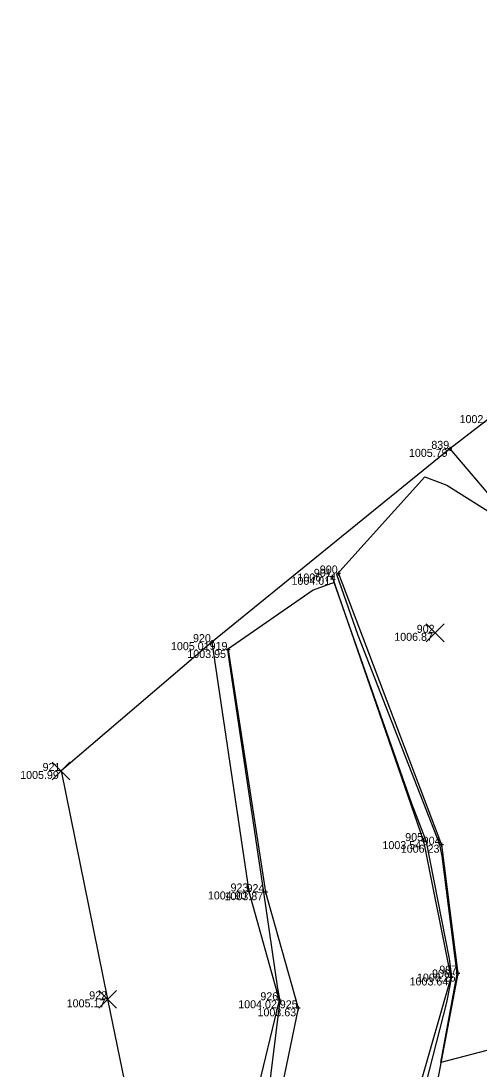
# Model space of a CAD drawing. Extents: x 2354693 to 2355622, y 637071 to 710080.
# Drawn here: x 2355052.4 to 2355121.1, y 709416.4 to 709573.6 of the extents above; entities that cross this region are included whole.
import ezdxf

# ---------------------------------------------------------------- set-up
doc = ezdxf.new("R2010")
doc.units = 0
for name, color, linetype in [('Default', 7, 'Continuous'), ('DT_X_Contour_Minor', 7, 'Continuous'), ('HY_X_Water_Edge', 7, 'Continuous'), ('SV_X_Random_Point', 7, 'Continuous'), ('SV_X_Shot_Marker', 7, 'Continuous'), ('SV_X_Text_Elevation', 7, 'Continuous'), ('SV_X_Text_Name', 7, 'Continuous'), ('SV_X_Toe_of_Slope', 7, 'Continuous'), ('SV_X_Top_of_Bank', 7, 'Continuous')]:
    doc.layers.add(name, color=color, linetype=linetype)

msp = doc.modelspace()

# ---------------------------------------------------------------- linework, layer by layer
at = {"layer": 'Default'}
msp.add_lwpolyline([(2355192.85, 709575.71), (2355160.05, 709542.81), (2355116.76, 709509.42), (2355081.06, 709480.43), (2355058.46, 709461.11), (2355065.45, 709426.86), (2355078.86, 709361.48), (2355116.19, 709325.77), (2355146.4, 709319.01), (2355178.16, 709243.86), (2355227.43, 709181.3), (2355213.36, 709127.54), (2355205.69, 709069.16), (2355203.89, 709062.28), (2355168.12, 708973.83)], dxfattribs=at)
msp.add_lwpolyline([(2355192.85, 709575.71), (2355160.05, 709542.81), (2355116.76, 709509.42), (2355081.06, 709480.43), (2355058.46, 709461.11), (2355065.45, 709426.86), (2355078.86, 709361.48), (2355116.19, 709325.77), (2355146.4, 709319.01), (2355178.16, 709243.86), (2355227.43, 709181.3), (2355213.36, 709127.54), (2355205.69, 709069.16), (2355203.89, 709062.28), (2355168.12, 708973.83)], dxfattribs=at)
at = {"layer": 'DT_X_Contour_Minor'}
for points in [[(2355136.74, 709486.86), (2355138.47, 709485.41), (2355148.81, 709475.1), (2355149.61, 709471.69), (2355151.16, 709446.51), (2355144.05, 709443.89), (2355145.69, 709438.94), (2355130.58, 709421.31), (2355115.44, 709417.4), (2355117.87, 709430.67), (2355115.64, 709448.31), (2355115.29, 709450.09), (2355103.02, 709481.45), (2355099.82, 709490.6), (2355113.01, 709505.22), (2355116.33, 709503.95), (2355127.34, 709497.01), (2355136.74, 709486.86)], [(2355136.74, 709486.86), (2355138.47, 709485.41), (2355148.81, 709475.1), (2355149.61, 709471.69), (2355151.16, 709446.51), (2355144.05, 709443.89), (2355145.69, 709438.94), (2355130.58, 709421.31), (2355115.44, 709417.4), (2355117.87, 709430.67), (2355115.64, 709448.31), (2355115.29, 709450.09), (2355103.02, 709481.45), (2355099.82, 709490.6), (2355113.01, 709505.22), (2355116.33, 709503.95), (2355127.34, 709497.01), (2355136.74, 709486.86)], [(2355111.69, 709408.23), (2355116.34, 709426.38), (2355117.05, 709430.22), (2355116.71, 709432.93), (2355113.29, 709450.49), (2355111.01, 709456.32), (2355099.44, 709489.36), (2355096.29, 709488.23), (2355083.41, 709479.32), (2355083.67, 709477.5), (2355088.8, 709442.95), (2355090.93, 709428.49), (2355091.27, 709426.68), (2355089.28, 709410.54)], [(2355111.69, 709408.23), (2355116.34, 709426.38), (2355117.05, 709430.22), (2355116.71, 709432.93), (2355113.29, 709450.49), (2355111.01, 709456.32), (2355099.44, 709489.36), (2355096.29, 709488.23), (2355083.41, 709479.32), (2355083.67, 709477.5), (2355088.8, 709442.95), (2355090.93, 709428.49), (2355091.27, 709426.68), (2355089.28, 709410.54)]]:
    msp.add_lwpolyline(points, dxfattribs=at)
at = {"layer": 'HY_X_Water_Edge'}
msp.add_lwpolyline([(2355099.14, 709490.23), (2355112.83, 709450.59), (2355116.9, 709430.14), (2355110.74, 709408.55), (2355107.27, 709364.38), (2355126.09, 709328.02), (2355146.4, 709319.01), (2355178.16, 709243.86), (2355207.27, 709238.41), (2355228.23, 709233.04), (2355237.12, 709206.89), (2355247.9, 709203.67), (2355256.61, 709243.12), (2355267.3, 709285.53), (2355279.14, 709298.91), (2355298.35, 709321.78), (2355310.42, 709328.49), (2355317.24, 709340.56)], dxfattribs=at)
at = {"layer": 'SV_X_Random_Point'}
for p, q in [((2355113.23, 709480.49), (2355115.9, 709483.16)), ((2355113.23, 709483.16), (2355115.9, 709480.49)), ((2355057.12, 709459.78), (2355059.79, 709462.45)), ((2355057.12, 709462.45), (2355059.79, 709459.78)), ((2355064.11, 709425.52), (2355066.78, 709428.19)), ((2355064.11, 709428.19), (2355066.78, 709425.52))]:
    msp.add_line(p, q, dxfattribs=at)
at = {"layer": 'SV_X_Shot_Marker'}
for p, q in [((2355117.06, 709509.42), (2355116.46, 709509.42)), ((2355116.76, 709509.72), (2355116.76, 709509.12)), ((2355099.14, 709490.53), (2355099.14, 709489.93)), ((2355100.38, 709490.73), (2355099.78, 709490.73)), ((2355100.08, 709491.03), (2355100.08, 709490.43)), ((2355099.44, 709490.23), (2355098.84, 709490.23)), ((2355081.36, 709480.43), (2355080.76, 709480.43)), ((2355081.06, 709480.73), (2355081.06, 709480.13)), ((2355083.82, 709479.26), (2355083.22, 709479.26)), ((2355083.52, 709479.56), (2355083.52, 709478.96)), ((2355113.13, 709450.59), (2355112.53, 709450.59)), ((2355112.83, 709450.89), (2355112.83, 709450.29)), ((2355115.82, 709450.05), (2355115.22, 709450.05)), ((2355115.52, 709450.35), (2355115.52, 709449.75)), ((2355086.64, 709443.34), (2355086.64, 709442.74)), ((2355089.1, 709443.23), (2355089.1, 709442.63)), ((2355086.94, 709443.04), (2355086.34, 709443.04)), ((2355089.4, 709442.93), (2355088.8, 709442.93)), ((2355118.28, 709430.72), (2355117.68, 709430.72)), ((2355117.98, 709431.02), (2355117.98, 709430.42)), ((2355117.2, 709430.14), (2355116.6, 709430.14)), ((2355116.9, 709430.44), (2355116.9, 709429.84)), ((2355091.45, 709426.72), (2355090.85, 709426.72)), ((2355091.15, 709427.02), (2355091.15, 709426.42)), ((2355094.33, 709425.51), (2355093.73, 709425.51)), ((2355094.03, 709425.81), (2355094.03, 709425.21))]:
    msp.add_line(p, q, dxfattribs=at)
at = {"layer": 'SV_X_Toe_of_Slope'}
for points in [[(2355099.14, 709490.23), (2355112.83, 709450.59), (2355116.9, 709430.14), (2355110.74, 709408.55), (2355107.27, 709364.38), (2355126.09, 709328.02), (2355146.4, 709319.01), (2355178.16, 709243.86), (2355207.27, 709238.41), (2355228.23, 709233.04), (2355237.12, 709206.89), (2355247.9, 709203.67), (2355256.61, 709243.12), (2355267.3, 709285.53), (2355279.14, 709298.91), (2355298.35, 709321.78), (2355310.42, 709328.49), (2355317.24, 709340.56)], [(2355083.52, 709479.26), (2355089.1, 709442.93), (2355094.03, 709425.51), (2355085.27, 709383.26), (2355093.95, 709361.08), (2355116.19, 709325.77)]]:
    msp.add_lwpolyline(points, dxfattribs=at)
at = {"layer": 'SV_X_Top_of_Bank'}
for points in [[(2355116.76, 709509.42), (2355137.58, 709484.99), (2355151.24, 709472.97), (2355164.56, 709477.47), (2355192.83, 709441.52), (2355225.93, 709388.87), (2355236.65, 709394.06)], [(2355100.08, 709490.73), (2355115.52, 709450.05), (2355117.98, 709430.72), (2355113.57, 709407.6), (2355111.71, 709364.49), (2355128.66, 709328.03), (2355150.44, 709319.86), (2355166.79, 709277.66), (2355166, 709276.87), (2355178.56, 709246.01), (2355206.83, 709240.61), (2355229.16, 709234.35), (2355238.05, 709208.04), (2355245.62, 709205.75), (2355249.4, 709246.95), (2355254.61, 709273.36), (2355264.37, 709286.54), (2355255.26, 709298.36), (2355265.16, 709308.45), (2355274.57, 709302.63), (2355292.81, 709328.24), (2355310.42, 709346), (2355315.95, 709345.13)], [(2355081.06, 709480.43), (2355086.64, 709443.04), (2355091.15, 709426.72), (2355080.82, 709383.86)]]:
    msp.add_lwpolyline(points, dxfattribs=at)

# ---------------------------------------------------------------- texts
at = {"layer": 'SV_X_Text_Elevation'}
for s, p in [('1002.93', (2355118.22, 709513.28)), ('1005.79', (2355110.63, 709508.22)), ('1006.74', (2355093.91, 709489.53)), ('1004.01', (2355093.02, 709489.03)), ('1006.87', (2355108.43, 709480.63)), ('1005.01', (2355074.94, 709479.23)), ('1003.95', (2355077.4, 709478.06)), ('1005.99', (2355052.33, 709459.91)), ('1003.54', (2355106.66, 709449.39)), ('1006.23', (2355109.41, 709448.85)), ('1004.90', (2355080.48, 709441.84)), ('1003.87', (2355082.97, 709441.73)), ('1006.26', (2355111.83, 709429.52)), ('1003.64', (2355110.73, 709428.94)), ('1005.17', (2355059.31, 709425.66)), ('1004.02', (2355085.03, 709425.52)), ('1003.63', (2355087.92, 709424.31))]:
    msp.add_text(s, height=1.2, dxfattribs=at).set_placement(p)
at = {"layer": 'SV_X_Text_Name'}
for s, p in [('839', (2355113.99, 709509.42)), ('900', (2355097.27, 709490.73)), ('901', (2355096.37, 709490.23)), ('902', (2355111.8, 709481.83)), ('920', (2355078.25, 709480.43)), ('919', (2355080.74, 709479.26)), ('921', (2355055.69, 709461.11)), ('905', (2355110.07, 709450.59)), ('904', (2355112.7, 709450.05)), ('923', (2355083.88, 709443.04)), ('924', (2355086.28, 709442.93)), ('906', (2355114.1, 709430.14)), ('907', (2355115.19, 709430.72)), ('922', (2355062.68, 709426.86)), ('926', (2355088.35, 709426.72)), ('925', (2355091.26, 709425.51))]:
    msp.add_text(s, height=1.2, dxfattribs=at).set_placement(p)

doc.saveas('drawing.dxf')
